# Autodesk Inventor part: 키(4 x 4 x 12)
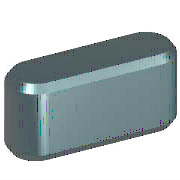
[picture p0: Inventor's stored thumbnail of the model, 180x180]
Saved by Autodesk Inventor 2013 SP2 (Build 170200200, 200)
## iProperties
IsCustomPart: 0
Created: 2009-02
Part Number: 키(4 x 4 x 12)
Material: 강철, 연강
Description: 키 및 해당 키홈
Document SubType Name: Modeling
Standard: KS B 1311
Designer: KYOUNG IL JANG
Standards Organization: KS
Language: ko-KR
Size Designation: 4 x 4 x 12
Categories: <MemberInstance><Categories><Category DisplayName="샤프트 부품" InternalName="7f7aeb1f-a693-4053-b835-cee3144e0d98" Mnemonic="SHFT"><Category DisplayName="키" Interna
Density: 7.86 g/cm^3
Mass: 1.38739 g
Surface Area: 1.94869 cm^2
Volume: 0.176513 cm^3
Author: KYOUNG IL JANG
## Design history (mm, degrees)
workplane "Work Plane1"
workplane "Work Plane2"
sketch "스케치1"
  geometry: L1 (2, 2)-(10, 2); L2 (10, -2)-(2, -2); L3 (0, 9.4)-(0, -7.4) reference; L4 (-5, 0)-(30, 0) reference; L5 (12, 0)-(12, 7); A1 r 2 centre (2, 0) between (2, 2) and (2, -2); A2 r 2 centre (10, 0) between (10, -2) and (10, 2)
  constraints: 6 end point, 5 point on circle, 4 tangent, 3 point on line, 2 centre point, 1 horizontal, 1 parallel, 1 perpendicular
  dimensions: "d0" = 2 radius of A1 (= 0.5 x PB); "d13" = 2 radius of A2 (= 0.5 x PB); "d14" = 12 distance between parallel lines of L5 L3 (= NLG)
extrude "본체1" new body sketch "스케치1" taper "d3" = 0 deg; stored distance "d4" = 10
workplane "Work Plane3"
body "Solid1"
chamfer "모따기1" distance "d8" = 0.25 (= PHH); stored, may be unused: second distance "d9" = 0.25 (= PHH), angle "d15" = 45 deg
other parameters: "d1" = -2.5 (= -PNT), "d2" = 1.5 (= PH - PNT), "NLG" = 12 [user parameter; used in 3 equation terms], "PB" = 4 [user parameter; used in 2 equation terms], "PNT" = 2.5 [user parameter; used in 2 equation terms], "PH" = 4 [user parameter; used in 1 equation term], "PHH" = 0.25 [user parameter; used in 2 equation terms], "d10" = 0, "d16" = 0, "d17" = 0, "d18" = 0, "PLB2" = 12 (= NLG) [user parameter], "WDMAX" = 12 [user parameter], "PLB1" = 12 (= NLG) [user parameter], "RR" = 0.08 [user parameter], "PUEB" = 1.8 [user parameter]
